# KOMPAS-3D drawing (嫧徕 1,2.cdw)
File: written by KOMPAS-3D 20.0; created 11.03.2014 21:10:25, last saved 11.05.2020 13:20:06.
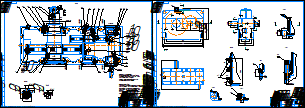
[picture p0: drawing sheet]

Sheets 1-2: A1, landscape

Document properties: Полное имя файла: C:\Users\Пользователь\Desktop\Осенний семестр 21-22(5 курс)\ТМП\для дз 2\Лист 1,2.cdw; Наименование: Редуктор двохступенчатый цилиндрический; Форматы листов документа: 2xA1

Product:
- Part/product: (unnamed)
  - Component: Подшипник 207  / ГОСТ 8338-75  | pos. 27  | Раздел спецификации: Стандартные изделия
  - Component: Болт М6 х 22  / ГОСТ 7805-70  | pos. 21  | Масса: 0.007204; Раздел спецификации: Стандартные изделия
  - Component: Штифт 8 х 36  / ГОСТ 3128-70  | pos. 36  | Раздел спецификации: Стандартные изделия
  - Component: Шайба 14 Н  / ГОСТ 6402-70  | pos. 30  | Масса: 0.00448; Раздел спецификации: Стандартные изделия
  - Component: Винт М14 х 75  / ГОСТ 11738-84  | pos. 23  | Масса: 0.11879; Раздел спецификации: Стандартные изделия
  - Component: Шпонка 22 х 14 х 63  / ГОСТ 23360-78  | pos. 34  | Масса: 0.1398; Раздел спецификации: Стандартные изделия
  - Component: Шпонка 8 х 7 х 22  / ГОСТ 23360-78  | pos. 32  | Масса: 0.00891; Раздел спецификации: Стандартные изделия
  - Component: Мaнжета 1-30 х 52-1  / ГОСТ 8752-79  | pos. 24  | Раздел спецификации: Стандартные изделия
  - Component: Подшипник 206  / ГОСТ 8338-75  | pos. 26  | Раздел спецификации: Стандартные изделия
  - Component: Мaнжета 1-65 х 90-1  / ГОСТ 8752-79  | pos. 25  | Раздел спецификации: Стандартные изделия
  - Component: Подшипник 213  / ГОСТ 8338-75  | pos. 28  | Раздел спецификации: Стандартные изделия
  - Component: Штифт 5 х 22  / ГОСТ 3128-70  | pos. 35  | Раздел спецификации: Стандартные изделия
  - Component: Шайба 8 Л  / ГОСТ 6402-70  | pos. 29  | Масса: 0.000827; Раздел спецификации: Стандартные изделия
  - Component: Болт М8 х 25 /  ГОСТ 7805-70  | pos. 22  | Масса: 0.01484; Раздел спецификации: Стандартные изделия
  - Component: Шайба 7019-0634 /  ГОСТ 14734-69  | pos. 31  | Раздел спецификации: Стандартные изделия
  - Component: Шпонка 16 х 10 х 80  / ГОСТ 23360-78  | pos. 33  | Масса: 0.09569; Раздел спецификации: Стандартные изделия

Title block, sheet 1: Наименование: Редуктор / двухступенчатый / цилиндрический; designation: ДМ 413-01.00.00 ВО; scale: 1:2; sheet number: 1; Количество листов документа: 2; Форматы листов документа: A1; stored path: E:\88119 Det M cyrsovoj\Чертеж.cdw
Title block, sheet 2: sheet number: 2

Views: Вид 1, Вид 2, Вид 3, Вид 4, Вид 5, Вид 6, Вид 7, Вид 8, Вид 9, Вид 10, Разрез 19, Разрез К-К
Referenced files in /: 8g, h9, r6, h11, k6, h8, d11
Referenced files in C:\Users\Пользователь\Desktop\Осенний семестр 21-22(5 курс)\ТМП\для дз 2\: Лист 1, 2 спец.spw
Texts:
  Symbol
  gliv
  2D_Doc-graphic.lyt,1.000000-0-351414899936
  2D_Doc-graphic.lyt,1.000000-0-286198296821
  2D_Doc-graphic.lyt,1.000000-0-351347510515
  2D_Doc-graphic.lyt,1.000000-0-354107535608
  2D_Doc-graphic.lyt,1.000000-0-349594944634
  2D_Doc-graphic.lyt,1.000000-0-349912230305
  2D_Doc-graphic.lyt,1.000000-0-356097139959
  2D_Doc-graphic.lyt,1.000000-0-346881367035
  2D_Doc-graphic.lyt,1.000000-0-349532490236
  2D_Doc-graphic.lyt,1.000000-0-349532490336
  2D_Doc-graphic.lyt,1.000000-0-348693045637
  2D_Doc-graphic.lyt,1.000000-0-347560468634
  Шпонка 16 х 10 х 80
  ГОСТ 23360-78
  Шпонка
  ГОСТ
  Шайба 7019-0634
  ГОСТ 14734-69
  Шайба кодированная
  Шайба
  2D_Doc-graphic.lyt,1.000000-0-355711749068
  Болт М8 х 25
  ГОСТ 7805-70
  Болт
  2D_Doc-graphic.lyt,1.000000-0-355936492910
  Шайба 8 Л
  ГОСТ 6402-70
  Шайба пружинная
  2D_Doc-graphic.lyt,1.000000-0-356318168824
  Штифт 5 х 22
  ГОСТ 3128-70
  Штифт
  Хим.Окс.прм
  2D_Doc-graphic.lyt,1.000000-0-355492662048
  Подшипник 213
  ГОСТ 8338-75
  Подшипник
  Мaнжета 1-65 х 90-1
  ГОСТ 8752-79
  Манжета
  Мaнжета
  Подшипник 206
  Мaнжета 1-30 х 52-1
  Шпонка 8 х 7 х 22
  Шпонка 22 х 14 х 63
  Винт М14 х 75
  ГОСТ 11738-84
  Винт
  Шайба 14 Н
  Штифт 8 х 36
  Болт М6 х 22
  Подшипник 207
Dimensions and other numbers on the sheet: 30; 1; 27; 20; 4отв.; 0,6; 18; 51; 146,5; 36; 8; 2отв.; 14; 16; 10; 53; 57; 6; 24,5; 22; 2; 3; 4; 5; 7; 9; 11; 12; 13; 15; 17; 19; 28; 25; 26; 24; 32; 34; 23; 76; 120; 90; 65; 35; 72; 38; 62; 52; 33; 40; 400; 125±0,03; 190±0,05; 218; 428; 522; 465; 578; 565; 110; 166; 210; 75; 21; 78; 7019-0; 69; -6g; 70; 65Г; 029; 84; 1:2

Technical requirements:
  Техническая характеристика
  1. Вращающий момент на тихоходном валу, Нм................................. 1192,0
  2. Частота вращения тихоходного вала, 1/мин............................ 31,0
  3. Передаточное число редуктора..................................................................   30,882
  4. Степень точности изготовления передач...................................  8
  5. Коефициент полезного действия............................................................. 0,886
  Технические требования
  Наружные поверхности красить эмалью ПФ-115 ГОСТ 6465-76
  Необработанные поверхности литых деталей, находящиеся в
  масляной ванне, красить маслостойкой эмалью.
  Плоскость разъема покрыть тонким слоем герметика УТ ГОСТ
  В редуктор залить масло И-Г-А-32 ГОСТ20799-88, объем 17л
  Для устранения осевого зазора использовать компенсаторы.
